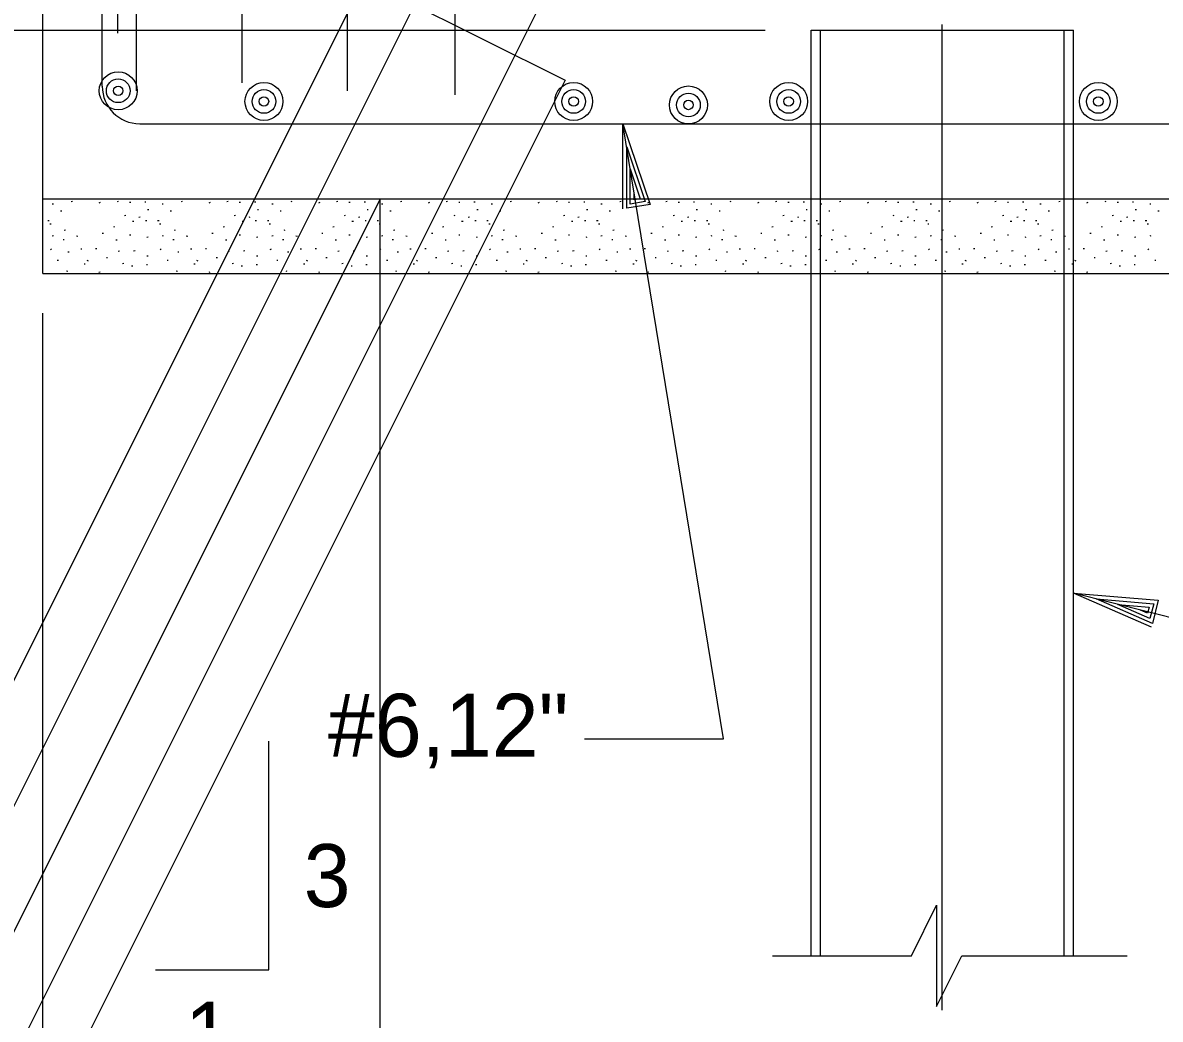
# Model space of a CAD drawing. Extents: x 6 to 106, y 3 to 74.
# Drawn here: x 84.18 to 90.92, y 51.44 to 57.35 of the extents above; entities that cross this region are included whole.
import ezdxf

# ---------------------------------------------------------------- set-up
doc = ezdxf.new("R2010")
doc.units = 0
for name, color, linetype in [('Level 13', 7, 'Continuous'), ('Level 22', 7, 'Continuous'), ('Level 44', 7, 'Continuous'), ('Level 50', 7, 'Continuous')]:
    doc.layers.add(name, color=color, linetype=linetype)

msp = doc.modelspace()

# ---------------------------------------------------------------- linework, layer by layer
at = {"layer": 'Level 13'}
msp.add_lwpolyline([(89.4456, 51.8173), (89.5946, 52.1173), (89.5946, 51.518), (89.7446, 51.8173)], dxfattribs=at)
at = {"layer": 'Level 22'}
for p, q in [((84.2951, 55.863), (84.2951, 68.974)), ((85.4757, 56.994), (85.4757, 68.835)), ((86.1007, 56.9477), (86.1007, 68.835)), ((84.8507, 56.9477), (84.8507, 68.7628)), ((86.7396, 56.9227), (86.7396, 68.7772)), ((84.7396, 57.2881), (84.7396, 58.9741)), ((84.6469, 56.9741), (84.6469, 58.8421)), ((86.8676, 58.1978), (83.4296, 51.3218)), ((87.4966, 57.9651), (84.0258, 51.0237)), ((86.1988, 57.6056), (83.1314, 51.4709)), ((86.1988, 57.6056), (87.3913, 57.0093)), ((80.4529, 57.3074), (88.5783, 57.3074)), ((88.8506, 57.3074), (90.4061, 57.3074)), ((88.8506, 51.8173), (88.8506, 57.3074)), ((88.9061, 51.8173), (88.9061, 57.3074)), ((89.6283, 51.496), (89.6283, 57.3411)), ((90.3505, 51.8173), (90.3505, 57.3074)), ((90.4061, 51.8173), (90.4061, 57.3074)), ((87.3913, 57.0093), (84.324, 50.8746)), ((84.8691, 56.7519), (94.2022, 56.7519)), ((88.3313, 53.1036), (87.7346, 56.7519)), ((86.2951, 56.3074), (82.7626, 49.2426)), ((84.2951, 56.3074), (94.9615, 56.3074)), ((86.2951, 49.6238), (86.2951, 56.3074)), ((84.2951, 55.863), (94.9615, 55.863)), ((84.2951, 47.9462), (84.2951, 55.6279)), ((96.5986, 52.3917), (90.4061, 53.9691)), ((87.5065, 53.1036), (88.3313, 53.1036)), ((85.6346, 51.7353), (85.6346, 53.0909)), ((88.6211, 51.8173), (89.4456, 51.8173)), ((89.7446, 51.8173), (90.7254, 51.8173)), ((84.9629, 51.7353), (85.6346, 51.7353))]:
    msp.add_line(p, q, dxfattribs=at)
msp.add_arc((84.8691, 56.9741), 0.2222, 180, 270, dxfattribs=at)
at = {"layer": 'Level 44'}
for p, q in [((84.3577, 56.2753), (84.3504, 56.2748)), ((84.4702, 56.29), (84.4629, 56.2895)), ((84.6349, 56.284), (84.627, 56.28)), ((84.7419, 56.29), (84.7345, 56.2895)), ((84.8154, 56.2852), (84.808, 56.2845)), ((84.9059, 56.2877), (84.8985, 56.287)), ((85.0085, 56.2753), (85.0012, 56.2748)), ((85.121, 56.29), (85.1137, 56.2895)), ((85.2857, 56.284), (85.2779, 56.28)), ((85.3927, 56.29), (85.3854, 56.2895)), ((85.4662, 56.2852), (85.4589, 56.2845)), ((85.5567, 56.2877), (85.5494, 56.287)), ((85.6594, 56.2753), (85.652, 56.2748)), ((85.7719, 56.29), (85.7645, 56.2895)), ((85.9365, 56.284), (85.9287, 56.28)), ((86.0435, 56.29), (86.0362, 56.2895)), ((86.117, 56.2852), (86.1097, 56.2845)), ((86.2075, 56.2877), (86.2002, 56.287)), ((86.3102, 56.2753), (86.3029, 56.2748)), ((86.4227, 56.29), (86.4154, 56.2895)), ((86.5874, 56.284), (86.5795, 56.28)), ((86.6944, 56.29), (86.687, 56.2895)), ((86.7679, 56.2852), (86.7605, 56.2845)), ((86.8584, 56.2877), (86.851, 56.287)), ((86.961, 56.2753), (86.9537, 56.2748)), ((87.0735, 56.29), (87.0662, 56.2895)), ((87.2382, 56.284), (87.2304, 56.28)), ((87.3452, 56.29), (87.3379, 56.2895)), ((87.4187, 56.2852), (87.4114, 56.2845)), ((87.5092, 56.2877), (87.5019, 56.287)), ((87.6119, 56.2753), (87.6045, 56.2748)), ((87.7244, 56.29), (87.717, 56.2895)), ((87.889, 56.284), (87.8812, 56.28)), ((87.996, 56.29), (87.9887, 56.2895)), ((88.0695, 56.2852), (88.0622, 56.2845)), ((88.16, 56.2877), (88.1527, 56.287)), ((88.2627, 56.2753), (88.2554, 56.2748)), ((88.3752, 56.29), (88.3679, 56.2895)), ((88.5399, 56.284), (88.532, 56.28)), ((88.6469, 56.29), (88.6395, 56.2895)), ((88.7204, 56.2852), (88.713, 56.2845)), ((88.8109, 56.2877), (88.8035, 56.287)), ((88.9135, 56.2753), (88.9062, 56.2748)), ((89.026, 56.29), (89.0187, 56.2895)), ((89.1907, 56.284), (89.1829, 56.28)), ((89.2977, 56.29), (89.2904, 56.2895)), ((89.3712, 56.2852), (89.3639, 56.2845)), ((89.4617, 56.2877), (89.4544, 56.287)), ((89.5644, 56.2753), (89.557, 56.2748)), ((89.6769, 56.29), (89.6695, 56.2895)), ((89.8415, 56.284), (89.8337, 56.28)), ((89.9485, 56.29), (89.9412, 56.2895)), ((90.022, 56.2852), (90.0147, 56.2845)), ((90.1125, 56.2877), (90.1052, 56.287)), ((90.2152, 56.2753), (90.2079, 56.2748)), ((90.3277, 56.29), (90.3204, 56.2895)), ((90.4924, 56.284), (90.4845, 56.28)), ((90.5994, 56.29), (90.592, 56.2895)), ((90.6729, 56.2852), (90.6655, 56.2845)), ((90.7634, 56.2877), (90.756, 56.287)), ((90.866, 56.2753), (90.8587, 56.2748)), ((84.4067, 56.2338), (84.3994, 56.2332)), ((84.786, 56.207), (84.7787, 56.2063)), ((84.8717, 56.197), (84.8644, 56.1965)), ((84.9229, 56.2412), (84.9155, 56.2405)), ((85.0575, 56.2338), (85.0502, 56.2332)), ((85.4369, 56.207), (85.4295, 56.2063)), ((85.5225, 56.197), (85.5152, 56.1965)), ((85.5737, 56.2412), (85.5664, 56.2405)), ((85.7084, 56.2338), (85.701, 56.2332)), ((86.0877, 56.207), (86.0804, 56.2063)), ((86.1734, 56.197), (86.166, 56.1965)), ((86.2245, 56.2412), (86.2172, 56.2405)), ((86.3592, 56.2338), (86.3519, 56.2332)), ((86.7385, 56.207), (86.7312, 56.2063)), ((86.8242, 56.197), (86.8169, 56.1965)), ((86.8754, 56.2412), (86.868, 56.2405)), ((87.01, 56.2338), (87.0027, 56.2332)), ((87.3894, 56.207), (87.382, 56.2063)), ((87.475, 56.197), (87.4677, 56.1965)), ((87.5262, 56.2412), (87.5189, 56.2405)), ((87.6609, 56.2338), (87.6535, 56.2332)), ((88.0402, 56.207), (88.0329, 56.2063)), ((88.1259, 56.197), (88.1185, 56.1965)), ((88.177, 56.2412), (88.1697, 56.2405)), ((88.3117, 56.2338), (88.3044, 56.2332)), ((88.691, 56.207), (88.6837, 56.2063)), ((88.7767, 56.197), (88.7694, 56.1965)), ((88.8279, 56.2412), (88.8205, 56.2405)), ((88.9625, 56.2338), (88.9552, 56.2332)), ((89.3419, 56.207), (89.3345, 56.2063)), ((89.4275, 56.197), (89.4202, 56.1965)), ((89.4787, 56.2412), (89.4714, 56.2405)), ((89.6134, 56.2338), (89.606, 56.2332)), ((89.9927, 56.207), (89.9854, 56.2063)), ((90.0784, 56.197), (90.071, 56.1965)), ((90.1295, 56.2412), (90.1222, 56.2405)), ((90.2642, 56.2338), (90.2569, 56.2332)), ((90.6435, 56.207), (90.6362, 56.2063)), ((90.7292, 56.197), (90.7219, 56.1965)), ((90.7804, 56.2412), (90.773, 56.2405)), ((90.915, 56.2338), (90.9077, 56.2332)), ((84.3327, 56.1765), (84.3244, 56.1765)), ((84.343, 56.157), (84.3357, 56.1565)), ((84.72, 56.14), (84.7127, 56.1393)), ((84.8344, 56.1728), (84.8254, 56.1728)), ((84.9109, 56.1765), (84.9034, 56.176)), ((84.9835, 56.1765), (84.9752, 56.1765)), ((84.9939, 56.157), (84.9865, 56.1565)), ((85.3709, 56.14), (85.3635, 56.1393)), ((85.4852, 56.1728), (85.4762, 56.1728)), ((85.5617, 56.1765), (85.5542, 56.176)), ((85.6344, 56.1765), (85.626, 56.1765)), ((85.6447, 56.157), (85.6374, 56.1565)), ((86.0217, 56.14), (86.0144, 56.1393)), ((86.136, 56.1728), (86.127, 56.1728)), ((86.2125, 56.1765), (86.205, 56.176)), ((86.2852, 56.1765), (86.2769, 56.1765)), ((86.2955, 56.157), (86.2882, 56.1565)), ((86.6725, 56.14), (86.6652, 56.1393)), ((86.7869, 56.1728), (86.7779, 56.1728)), ((86.8634, 56.1765), (86.8559, 56.176)), ((86.936, 56.1765), (86.9277, 56.1765)), ((86.9464, 56.157), (86.939, 56.1565)), ((87.3234, 56.14), (87.316, 56.1393)), ((87.4377, 56.1728), (87.4287, 56.1728)), ((87.5142, 56.1765), (87.5067, 56.176)), ((87.5869, 56.1765), (87.5785, 56.1765)), ((87.5972, 56.157), (87.5899, 56.1565)), ((87.9742, 56.14), (87.9669, 56.1393)), ((88.0885, 56.1728), (88.0795, 56.1728)), ((88.165, 56.1765), (88.1575, 56.176)), ((88.2377, 56.1765), (88.2294, 56.1765)), ((88.248, 56.157), (88.2407, 56.1565)), ((88.625, 56.14), (88.6177, 56.1393)), ((88.7394, 56.1728), (88.7304, 56.1728)), ((88.8159, 56.1765), (88.8084, 56.176)), ((88.8885, 56.1765), (88.8802, 56.1765)), ((88.8989, 56.157), (88.8915, 56.1565)), ((89.2759, 56.14), (89.2685, 56.1393)), ((89.3902, 56.1728), (89.3812, 56.1728)), ((89.4667, 56.1765), (89.4592, 56.176)), ((89.5394, 56.1765), (89.531, 56.1765)), ((89.5497, 56.157), (89.5424, 56.1565)), ((89.9267, 56.14), (89.9194, 56.1393)), ((90.041, 56.1728), (90.032, 56.1728)), ((90.1175, 56.1765), (90.11, 56.176)), ((90.1902, 56.1765), (90.1819, 56.1765)), ((90.2005, 56.157), (90.1932, 56.1565)), ((90.5775, 56.14), (90.5702, 56.1393)), ((90.6919, 56.1728), (90.6829, 56.1728)), ((90.7684, 56.1765), (90.7609, 56.176)), ((90.841, 56.1765), (90.8327, 56.1765)), ((90.8514, 56.157), (90.844, 56.1565)), ((84.3577, 56.0862), (84.3504, 56.0855)), ((84.4214, 56.064), (84.414, 56.0635)), ((84.4287, 56.1203), (84.4214, 56.1197)), ((84.5025, 56.0828), (84.4939, 56.0842)), ((84.6539, 56.1008), (84.6465, 56.1002)), ((84.7345, 56.0617), (84.7272, 56.061)), ((84.8154, 56.091), (84.808, 56.0905)), ((84.9182, 56.0788), (84.9109, 56.0782)), ((85.0085, 56.0862), (85.0012, 56.0855)), ((85.0722, 56.064), (85.0649, 56.0635)), ((85.0795, 56.1203), (85.0722, 56.1197)), ((85.1534, 56.0828), (85.1447, 56.0842)), ((85.3047, 56.1008), (85.2974, 56.1002)), ((85.3854, 56.0617), (85.378, 56.061)), ((85.4662, 56.091), (85.4589, 56.0905)), ((85.569, 56.0788), (85.5617, 56.0782)), ((85.6594, 56.0862), (85.652, 56.0855)), ((85.723, 56.064), (85.7157, 56.0635)), ((85.7304, 56.1203), (85.723, 56.1197)), ((85.8042, 56.0828), (85.7955, 56.0842)), ((85.9555, 56.1008), (85.9482, 56.1002)), ((86.0362, 56.0617), (86.0289, 56.061)), ((86.117, 56.091), (86.1097, 56.0905)), ((86.2199, 56.0788), (86.2125, 56.0782)), ((86.3102, 56.0862), (86.3029, 56.0855)), ((86.3739, 56.064), (86.3665, 56.0635)), ((86.3812, 56.1203), (86.3739, 56.1197)), ((86.455, 56.0828), (86.4464, 56.0842)), ((86.6064, 56.1008), (86.599, 56.1002)), ((86.687, 56.0617), (86.6797, 56.061)), ((86.7679, 56.091), (86.7605, 56.0905)), ((86.8707, 56.0788), (86.8634, 56.0782)), ((86.961, 56.0862), (86.9537, 56.0855)), ((87.0247, 56.064), (87.0174, 56.0635)), ((87.032, 56.1203), (87.0247, 56.1197)), ((87.1059, 56.0828), (87.0972, 56.0842)), ((87.2572, 56.1008), (87.2499, 56.1002)), ((87.3379, 56.0617), (87.3305, 56.061)), ((87.4187, 56.091), (87.4114, 56.0905)), ((87.5215, 56.0788), (87.5142, 56.0782)), ((87.6119, 56.0862), (87.6045, 56.0855)), ((87.6755, 56.064), (87.6682, 56.0635)), ((87.6829, 56.1203), (87.6755, 56.1197)), ((87.7567, 56.0828), (87.748, 56.0842)), ((87.908, 56.1008), (87.9007, 56.1002)), ((87.9887, 56.0617), (87.9814, 56.061)), ((88.0695, 56.091), (88.0622, 56.0905)), ((88.1724, 56.0788), (88.165, 56.0782)), ((88.2627, 56.0862), (88.2554, 56.0855)), ((88.3264, 56.064), (88.319, 56.0635)), ((88.3337, 56.1203), (88.3264, 56.1197)), ((88.4075, 56.0828), (88.3989, 56.0842)), ((88.5589, 56.1008), (88.5515, 56.1002)), ((88.6395, 56.0617), (88.6322, 56.061)), ((88.7204, 56.091), (88.713, 56.0905)), ((88.8232, 56.0788), (88.8159, 56.0782)), ((88.9135, 56.0862), (88.9062, 56.0855)), ((88.9772, 56.064), (88.9699, 56.0635)), ((88.9845, 56.1203), (88.9772, 56.1197)), ((89.0584, 56.0828), (89.0497, 56.0842)), ((89.2097, 56.1008), (89.2024, 56.1002)), ((89.2904, 56.0617), (89.283, 56.061)), ((89.3712, 56.091), (89.3639, 56.0905)), ((89.474, 56.0788), (89.4667, 56.0782)), ((89.5644, 56.0862), (89.557, 56.0855)), ((89.628, 56.064), (89.6207, 56.0635)), ((89.6354, 56.1203), (89.628, 56.1197)), ((89.7092, 56.0828), (89.7005, 56.0842)), ((89.8605, 56.1008), (89.8532, 56.1002)), ((89.9412, 56.0617), (89.9339, 56.061)), ((90.022, 56.091), (90.0147, 56.0905)), ((90.1249, 56.0788), (90.1175, 56.0782)), ((90.2152, 56.0862), (90.2079, 56.0855)), ((90.2789, 56.064), (90.2715, 56.0635)), ((90.2862, 56.1203), (90.2789, 56.1197)), ((90.36, 56.0828), (90.3514, 56.0842)), ((90.5114, 56.1008), (90.504, 56.1002)), ((90.592, 56.0617), (90.5847, 56.061)), ((90.6729, 56.091), (90.6655, 56.0905)), ((90.7757, 56.0788), (90.7684, 56.0782)), ((90.866, 56.0862), (90.8587, 56.0855)), ((84.3459, 56.0072), (84.3395, 56.0047)), ((84.5265, 56.0078), (84.5192, 56.0072)), ((84.6147, 56.0102), (84.6074, 56.0097)), ((84.7492, 55.9957), (84.7419, 55.995)), ((84.8415, 55.9982), (84.8325, 55.9957)), ((84.9967, 56.0072), (84.9904, 56.0047)), ((85.1774, 56.0078), (85.17, 56.0072)), ((85.2655, 56.0102), (85.2582, 56.0097)), ((85.4, 55.9957), (85.3927, 55.995)), ((85.4924, 55.9982), (85.4834, 55.9957)), ((85.6475, 56.0072), (85.6412, 56.0047)), ((85.8282, 56.0078), (85.8209, 56.0072)), ((85.9164, 56.0102), (85.909, 56.0097)), ((86.0509, 55.9957), (86.0435, 55.995)), ((86.1432, 55.9982), (86.1342, 55.9957)), ((86.2984, 56.0072), (86.292, 56.0047)), ((86.479, 56.0078), (86.4717, 56.0072)), ((86.5672, 56.0102), (86.5599, 56.0097)), ((86.7017, 55.9957), (86.6944, 55.995)), ((86.794, 55.9982), (86.785, 55.9957)), ((86.9492, 56.0072), (86.9429, 56.0047)), ((87.1299, 56.0078), (87.1225, 56.0072)), ((87.218, 56.0102), (87.2107, 56.0097)), ((87.3525, 55.9957), (87.3452, 55.995)), ((87.4449, 55.9982), (87.4359, 55.9957)), ((87.6, 56.0072), (87.5937, 56.0047)), ((87.7807, 56.0078), (87.7734, 56.0072)), ((87.8689, 56.0102), (87.8615, 56.0097)), ((88.0034, 55.9957), (87.996, 55.995)), ((88.0957, 55.9982), (88.0867, 55.9957)), ((88.2509, 56.0072), (88.2445, 56.0047)), ((88.4315, 56.0078), (88.4242, 56.0072)), ((88.5197, 56.0102), (88.5124, 56.0097)), ((88.6542, 55.9957), (88.6469, 55.995)), ((88.7465, 55.9982), (88.7375, 55.9957)), ((88.9017, 56.0072), (88.8954, 56.0047)), ((89.0824, 56.0078), (89.075, 56.0072)), ((89.1705, 56.0102), (89.1632, 56.0097)), ((89.305, 55.9957), (89.2977, 55.995)), ((89.3974, 55.9982), (89.3884, 55.9957)), ((89.5525, 56.0072), (89.5462, 56.0047)), ((89.7332, 56.0078), (89.7259, 56.0072)), ((89.8214, 56.0102), (89.814, 56.0097)), ((89.9559, 55.9957), (89.9485, 55.995)), ((90.0482, 55.9982), (90.0392, 55.9957)), ((90.2034, 56.0072), (90.197, 56.0047)), ((90.384, 56.0078), (90.3767, 56.0072)), ((90.4722, 56.0102), (90.4649, 56.0097)), ((90.6067, 55.9957), (90.5994, 55.995)), ((90.699, 55.9982), (90.69, 55.9957)), ((90.8542, 56.0072), (90.8479, 56.0047)), ((84.3872, 55.9418), (84.3799, 55.9412)), ((84.4507, 55.9907), (84.4434, 55.9902)), ((84.5647, 55.9365), (84.5572, 55.941)), ((84.6784, 55.9565), (84.6709, 55.956)), ((84.9182, 55.9663), (84.9109, 55.9657)), ((85.038, 55.9418), (85.0307, 55.9412)), ((85.1015, 55.9907), (85.0942, 55.9902)), ((85.2155, 55.9365), (85.208, 55.941)), ((85.3292, 55.9565), (85.3217, 55.956)), ((85.569, 55.9663), (85.5617, 55.9657)), ((85.6889, 55.9418), (85.6815, 55.9412)), ((85.7524, 55.9907), (85.745, 55.9902)), ((85.8664, 55.9365), (85.8589, 55.941)), ((85.98, 55.9565), (85.9725, 55.956)), ((86.2199, 55.9663), (86.2125, 55.9657)), ((86.3397, 55.9418), (86.3324, 55.9412)), ((86.4032, 55.9907), (86.3959, 55.9902)), ((86.5172, 55.9365), (86.5097, 55.941)), ((86.6309, 55.9565), (86.6234, 55.956)), ((86.8707, 55.9663), (86.8634, 55.9657)), ((86.9905, 55.9418), (86.9832, 55.9412)), ((87.054, 55.9907), (87.0467, 55.9902)), ((87.168, 55.9365), (87.1605, 55.941)), ((87.2817, 55.9565), (87.2742, 55.956)), ((87.5215, 55.9663), (87.5142, 55.9657)), ((87.6414, 55.9418), (87.634, 55.9412)), ((87.7049, 55.9907), (87.6975, 55.9902)), ((87.8189, 55.9365), (87.8114, 55.941)), ((87.9325, 55.9565), (87.925, 55.956)), ((88.1724, 55.9663), (88.165, 55.9657)), ((88.2922, 55.9418), (88.2849, 55.9412)), ((88.3557, 55.9907), (88.3484, 55.9902)), ((88.4697, 55.9365), (88.4622, 55.941)), ((88.5834, 55.9565), (88.5759, 55.956)), ((88.8232, 55.9663), (88.8159, 55.9657)), ((88.943, 55.9418), (88.9357, 55.9412)), ((89.0065, 55.9907), (88.9992, 55.9902)), ((89.1205, 55.9365), (89.113, 55.941)), ((89.2342, 55.9565), (89.2267, 55.956)), ((89.474, 55.9663), (89.4667, 55.9657)), ((89.5939, 55.9418), (89.5865, 55.9412)), ((89.6574, 55.9907), (89.65, 55.9902)), ((89.7714, 55.9365), (89.7639, 55.941)), ((89.885, 55.9565), (89.8775, 55.956)), ((90.1249, 55.9663), (90.1175, 55.9657)), ((90.2447, 55.9418), (90.2374, 55.9412)), ((90.3082, 55.9907), (90.3009, 55.9902)), ((90.4222, 55.9365), (90.4147, 55.941)), ((90.5359, 55.9565), (90.5284, 55.956)), ((90.7757, 55.9663), (90.7684, 55.9657)), ((90.8955, 55.9418), (90.8882, 55.9412)), ((84.442, 55.8747), (84.435, 55.878)), ((84.5462, 55.9198), (84.5389, 55.9192)), ((84.6344, 55.8708), (84.627, 55.8703)), ((84.7737, 55.9222), (84.7664, 55.9215)), ((84.8275, 55.9077), (84.8202, 55.907)), ((84.9155, 55.9148), (84.9082, 55.9142)), ((85.0929, 55.8747), (85.0859, 55.878)), ((85.197, 55.9198), (85.1897, 55.9192)), ((85.2852, 55.8708), (85.2779, 55.8703)), ((85.4245, 55.9222), (85.4172, 55.9215)), ((85.4784, 55.9077), (85.471, 55.907)), ((85.5664, 55.9148), (85.559, 55.9142)), ((85.7437, 55.8747), (85.7367, 55.878)), ((85.8479, 55.9198), (85.8405, 55.9192)), ((85.936, 55.8708), (85.9287, 55.8703)), ((86.0754, 55.9222), (86.068, 55.9215)), ((86.1292, 55.9077), (86.1219, 55.907)), ((86.2172, 55.9148), (86.2099, 55.9142)), ((86.3945, 55.8747), (86.3875, 55.878)), ((86.4987, 55.9198), (86.4914, 55.9192)), ((86.5869, 55.8708), (86.5795, 55.8703)), ((86.7262, 55.9222), (86.7189, 55.9215)), ((86.78, 55.9077), (86.7727, 55.907)), ((86.868, 55.9148), (86.8607, 55.9142)), ((87.0454, 55.8747), (87.0384, 55.878)), ((87.1495, 55.9198), (87.1422, 55.9192)), ((87.2377, 55.8708), (87.2304, 55.8703)), ((87.377, 55.9222), (87.3697, 55.9215)), ((87.4309, 55.9077), (87.4235, 55.907)), ((87.5189, 55.9148), (87.5115, 55.9142)), ((87.6962, 55.8747), (87.6892, 55.878)), ((87.8004, 55.9198), (87.793, 55.9192)), ((87.8885, 55.8708), (87.8812, 55.8703)), ((88.0279, 55.9222), (88.0205, 55.9215)), ((88.0817, 55.9077), (88.0744, 55.907)), ((88.1697, 55.9148), (88.1624, 55.9142)), ((88.347, 55.8747), (88.34, 55.878)), ((88.4512, 55.9198), (88.4439, 55.9192)), ((88.5394, 55.8708), (88.532, 55.8703)), ((88.6787, 55.9222), (88.6714, 55.9215)), ((88.7325, 55.9077), (88.7252, 55.907)), ((88.8205, 55.9148), (88.8132, 55.9142)), ((88.9979, 55.8747), (88.9909, 55.878)), ((89.102, 55.9198), (89.0947, 55.9192)), ((89.1902, 55.8708), (89.1829, 55.8703)), ((89.3295, 55.9222), (89.3222, 55.9215)), ((89.3834, 55.9077), (89.376, 55.907)), ((89.4714, 55.9148), (89.464, 55.9142)), ((89.6487, 55.8747), (89.6417, 55.878)), ((89.7529, 55.9198), (89.7455, 55.9192)), ((89.841, 55.8708), (89.8337, 55.8703)), ((89.9804, 55.9222), (89.973, 55.9215)), ((90.0342, 55.9077), (90.0269, 55.907)), ((90.1222, 55.9148), (90.1149, 55.9142)), ((90.2995, 55.8747), (90.2925, 55.878)), ((90.4037, 55.9198), (90.3964, 55.9192)), ((90.4919, 55.8708), (90.4845, 55.8703)), ((90.6312, 55.9222), (90.6239, 55.9215)), ((90.685, 55.9077), (90.6777, 55.907)), ((90.773, 55.9148), (90.7657, 55.9142))]:
    msp.add_line(p, q, dxfattribs=at)
at = {"layer": 'Level 50'}
for p, q in [((87.7346, 56.7519), (87.7346, 56.7519)), ((87.757, 56.615), (87.757, 56.615)), ((90.4061, 53.9691), (90.4061, 53.9691)), ((90.5405, 53.9349), (90.5405, 53.9349))]:
    msp.add_line(p, q, dxfattribs=at)
for points in [[(87.7335, 56.2464), (87.7346, 56.7519), (87.8967, 56.2731), (87.7572, 56.2503), (87.757, 56.615), (87.8669, 56.2899), (87.7774, 56.2752), (87.7785, 56.4834), (87.8372, 56.3066), (87.8003, 56.3006), (87.8009, 56.3466)], [(90.8689, 53.7659), (90.4061, 53.9691), (90.9097, 53.9261), (90.8748, 53.7891), (90.5405, 53.9349), (90.8825, 53.9055), (90.8601, 53.8177), (90.6697, 53.9019), (90.8552, 53.8849), (90.846, 53.8488), (90.804, 53.8677)]]:
    msp.add_lwpolyline(points, dxfattribs=at)
for centre, radius in [((84.7413, 56.9471), 0.1125), ((84.7413, 56.9471), 0.0703), ((84.7413, 56.9471), 0.0281), ((85.6057, 56.8841), 0.1125), ((85.6057, 56.8841), 0.0703), ((87.4424, 56.8841), 0.1125), ((87.4424, 56.8841), 0.0703), ((88.1231, 56.8631), 0.1125), ((88.7174, 56.8841), 0.1125), ((88.7174, 56.8841), 0.0703), ((90.5541, 56.8841), 0.1125), ((90.5541, 56.8841), 0.0703), ((85.6057, 56.8841), 0.0281), ((87.4424, 56.8841), 0.0281), ((88.1231, 56.8631), 0.0703), ((88.1231, 56.8631), 0.0281), ((88.7174, 56.8841), 0.0281), ((90.5541, 56.8841), 0.0281)]:
    msp.add_circle(centre, radius, dxfattribs=at)

# ---------------------------------------------------------------- texts
at = {"layer": 'Level 22'}
for s, height, p in [('#6,12"', 0.37333, (85.9856, 52.9982)), ('3', 0.3733, (85.8416, 52.1069)), ('1', 0.3733, (85.1367, 51.1718))]:
    msp.add_text(s, height=height, dxfattribs=at).set_placement(p)

doc.saveas('drawing.dxf')
